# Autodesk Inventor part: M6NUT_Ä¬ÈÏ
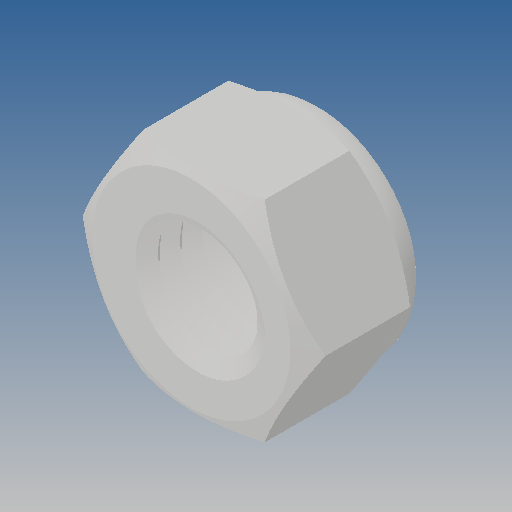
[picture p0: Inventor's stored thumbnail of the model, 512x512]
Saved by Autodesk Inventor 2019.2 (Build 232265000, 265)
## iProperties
Created: 2010-06
Part Number: M6NUT_Ä¬ÈÏ
Material: Ogólny
Document SubType Name: Modeling
Designer: CADENGINEERING4
Density: 1 g/cm^3
Appearance: Domyślna
Author: CADENGINEERING4
Revision Number: ÈÎºÎ
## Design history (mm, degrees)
feature "NONE"
node "Bryła1"
